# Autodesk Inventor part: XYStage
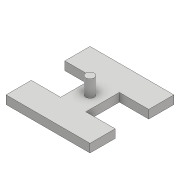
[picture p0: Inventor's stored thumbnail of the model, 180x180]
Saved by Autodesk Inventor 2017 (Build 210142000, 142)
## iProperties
Part Number: XYStage
Material: 一般
Document SubType Name: Modeling
Designer: kyushu-hep
Density: 1 g/cm^3
Appearance: 既定
Author: kyushu-hep
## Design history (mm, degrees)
sketch "スケッチ1"
  geometry: L1 (-50, 50)-(-50, 20); L2 (-50, 20)-(-15, 20); L3 (-15, 20)-(-15, -20); L4 (-15, -20)-(-50, -20); L5 (-50, -20)-(-50, -50); L6 (-50, -50)-(50, -50); L7 (50, -50)-(50, -20); L8 (50, -20)-(15, -20); L9 (15, -20)-(15, 20); L10 (15, 20)-(50, 20); L11 (50, 50)-(-50, 50); L12 (50, 50)-(50, 20); 1 further point
  constraints: 24 end point, 9 perpendicular, 4 point on line, 3 equal length, 1 collinear, 1 parallel, 1 vertical
  dimensions: "d0" = 50 distance from line of L11 point (0, 0); "d3" = 40 distance of L2.end L3.end; "d4" = 50 distance from line of point (0, 0) L1; "d5" = 100 distance of L11.start L1.start; "d6" = 100 distance between parallel lines of L6 L11; "d7" = 15 distance from line of point (0, 0) L3
extrude "押し出し1" new body sketch "スケッチ1" distance "d8" = 10; taper "d9" = 0 deg
sketch "スケッチ2"
  geometry: C1 r 5 at (0, 0); 1 further point
  constraints: 1 centre point, 1 coincident
  dimensions: "d10" = 10 diameter of C1
extrude "押し出し2" join sketch "スケッチ2" distance "d11" = 20; taper "d12" = 0 deg
node "ソリッド1"
